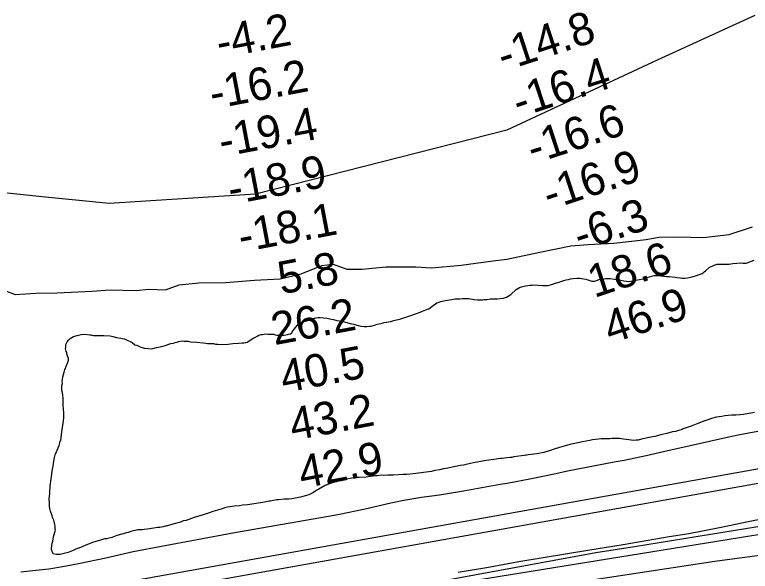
# Model space of a CAD drawing. Extents: x 3146026 to 3183936, y 897894 to 923344.
# Drawn here: x 3160766 to 3162279, y 910893 to 912037 of the extents above; entities that cross this region are included whole.
import ezdxf

# ---------------------------------------------------------------- set-up
doc = ezdxf.new("R2010")
doc.units = 0
for name, color, linetype in [('V-LEVE-TOET', 7, 'Continuous'), ('V-RIVR-EDGE', 7, 'Continuous'), ('V-RIVR-RANG', 7, 'Continuous'), ('V-ROAD-CNTR', 7, 'Continuous'), ('V-SITE-VEGE', 7, 'Continuous'), ('V-SURV-LINE', 7, 'Continuous'), ('V-TOPO-BNDY', 7, 'Continuous'), ('V-TOPO-SHOR', 7, 'Continuous')]:
    doc.layers.add(name, color=color, linetype=linetype)

msp = doc.modelspace()

# ---------------------------------------------------------------- linework, layer by layer
at = {"layer": 'V-LEVE-TOET'}
for points in [[(3162313.2, 911183.9), (3162257.1, 911173.5), (3162240.8, 911170.2), (3162109.2, 911140.5), (3162064.7, 911129.9), (3162019.8, 911120.8), (3161999.2, 911117.2), (3161902.9, 911098.3), (3161879, 911093.4), (3161829.2, 911082.6), (3161779, 911073.4), (3161764.6, 911071), (3161689.1, 911057.2), (3161639.6, 911049), (3161602.9, 911044.4), (3161566.5, 911038.3), (3161539.7, 911032.7), (3161487.2, 911020.2), (3161434.4, 911009.3), (3161423.5, 911007.3), (3161301.1, 910986.1), (3161215, 910971.3), (3161068.4, 910944), (3161010.1, 910933.1), (3160953.9, 910919.6), (3160901, 910908.5), (3160868.7, 910902.5), (3160836.2, 910897.5), (3160803.6, 910893.6), (3160779, 910891.2)], [(3162298.7, 910999.1), (3162277.9, 910995.3), (3162215.3, 910981.9), (3162152.3, 910970.1), (3162112.2, 910963.4), (3162017.4, 910946.9), (3161949.2, 910935.9), (3161802.9, 910912.3), (3161740.6, 910900.4), (3161678, 910890.1)]]:
    msp.add_lwpolyline(points, dxfattribs=at)
at = {"layer": 'V-RIVR-EDGE'}
msp.add_lwpolyline([(3160745.7, 911470), (3160767.1, 911462), (3160809.6, 911464.3), (3160853.6, 911465.4), (3160924.6, 911468.4), (3160962.3, 911471.5), (3161016.2, 911469.8), (3161041.6, 911472.5), (3161076.1, 911471.2), (3161104.7, 911481.8), (3161144.7, 911485.7), (3161200.3, 911486.3), (3161259.4, 911491.4), (3161312.1, 911494), (3161355.4, 911504.2), (3161397.8, 911521.6), (3161421.3, 911524.3), (3161449.4, 911513.9), (3161480.7, 911513.8), (3161529.5, 911518.8), (3161591.4, 911518.3), (3161623.5, 911516.6), (3161684.6, 911522), (3161744.5, 911530.2), (3161778.2, 911534.1), (3161846.1, 911548.6), (3161910, 911561.5), (3161945.3, 911564.2), (3161998.4, 911567.3), (3162064.7, 911574.6), (3162090.8, 911579.3), (3162130.5, 911580.4), (3162182.5, 911578.7), (3162235.2, 911584.9), (3162283.2, 911600.7)], dxfattribs=at)
at = {"layer": 'V-ROAD-CNTR'}
msp.add_lwpolyline([(3162638.2, 911023.4), (3161582.1, 910852.6), (3160471.1, 910632.1), (3159717.3, 910482.4)], dxfattribs=at)
at = {"layer": 'V-SITE-VEGE'}
for points in [[(3161758.3, 911453), (3161771.3, 911454.3), (3161777.6, 911456.5), (3161780.9, 911458.1), (3161786.4, 911462), (3161797.6, 911472.1), (3161804.3, 911476.3), (3161808.1, 911477.6), (3161816.5, 911479.7), (3161826.5, 911481.1), (3161829.5, 911481.1), (3161833.7, 911481.9), (3161851.3, 911480.4), (3161859.3, 911480), (3161862.6, 911480.4), (3161868.1, 911481.7), (3161874.3, 911483.4), (3161880.6, 911485.6), (3161884, 911486.4), (3161891.5, 911489), (3161895.3, 911490.7), (3161900.3, 911492), (3161904.9, 911492.8), (3161909.5, 911494.1), (3161914.1, 911494.6), (3161922.1, 911495), (3161927.6, 911495), (3161940.6, 911493), (3161952.8, 911488.9), (3161955.7, 911488.9), (3161959.1, 911489.4), (3161962.4, 911490.2), (3161967.9, 911492.3), (3161978.3, 911494.1), (3161981.7, 911494.9), (3161984.6, 911494.9), (3161988, 911494.5), (3161990.9, 911494.6), (3161999.7, 911493.4), (3162004.4, 911492.5), (3162006.5, 911492.6), (3162012.8, 911491.3), (3162018.6, 911489.7), (3162024.5, 911488.9), (3162029.1, 911488.5), (3162043.8, 911491.1), (3162051.3, 911492.8), (3162058.5, 911494.1), (3162062.2, 911495), (3162071.5, 911497.9), (3162081.1, 911500.5), (3162089.5, 911501), (3162106.7, 911499), (3162112.6, 911498.6), (3162124.3, 911497.4), (3162127.7, 911496.6), (3162135.7, 911495.8), (3162138.2, 911495.4), (3162144.5, 911495.4), (3162149.9, 911495.9), (3162159.6, 911498), (3162165.9, 911500.2), (3162174.2, 911502.7), (3162179.7, 911504.8), (3162182.2, 911506.5), (3162183.8, 911508.2), (3162186.8, 911510.3), (3162194.3, 911517.1), (3162204.8, 911522.2), (3162211, 911523.9), (3162226.1, 911524.4), (3162232.4, 911524), (3162234.9, 911524), (3162242.9, 911525.8), (3162259.7, 911526.7), (3162264.3, 911526.3), (3162270.2, 911526.3), (3162272.7, 911526.8), (3162286.9, 911532.3)], [(3161114.7, 911365.9), (3161122.7, 911365.5), (3161127.7, 911364.7), (3161140.8, 911364), (3161153.8, 911362.3), (3161159.2, 911362), (3161163, 911361.1), (3161168, 911361.2), (3161175.2, 911360.8), (3161179.4, 911360), (3161184, 911359.6), (3161194.1, 911359.2), (3161205, 911359.7), (3161215, 911361), (3161227.2, 911361.5), (3161233.9, 911362.4), (3161237.3, 911362.4), (3161240.2, 911363.2), (3161242.3, 911363.3), (3161244.4, 911364.1), (3161257.8, 911372.6), (3161259.9, 911373.4), (3161264.9, 911376), (3161268.2, 911378.1), (3161273.2, 911379.8), (3161275.8, 911379.8), (3161282.9, 911380.7), (3161286.7, 911380.3), (3161295.1, 911380.3), (3161299.3, 911379.9), (3161302.2, 911379.1), (3161305.6, 911377.9), (3161311.9, 911377.9), (3161320.7, 911378), (3161327, 911379.3), (3161329, 911380.1), (3161333.2, 911381), (3161336.2, 911383.1), (3161337, 911385.2), (3161339.1, 911387.7), (3161347, 911398.2), (3161351.2, 911402.5), (3161358.3, 911406.3), (3161361.6, 911406.3), (3161369.2, 911408), (3161372.9, 911409.3), (3161378.4, 911411.4), (3161385.5, 911413.6), (3161390.5, 911414.4), (3161394.7, 911414.5), (3161408.2, 911412.9), (3161417.8, 911411.2), (3161421.6, 911410.4), (3161428.8, 911408.4), (3161434.2, 911407.5), (3161438.8, 911406.7), (3161441.8, 911406.3), (3161446.8, 911404.7), (3161459, 911401.4), (3161463.6, 911400.6), (3161469.5, 911398.5), (3161472.9, 911398.1), (3161477.9, 911396.5), (3161485, 911395.7), (3161490.5, 911395.7), (3161496.8, 911396.6), (3161499.3, 911397), (3161508.1, 911399.6), (3161511.9, 911400.8), (3161515.6, 911401.7), (3161521.9, 911402.6), (3161526.1, 911403.9), (3161539.5, 911406.5), (3161546.2, 911408.2), (3161560.1, 911412), (3161574.7, 911416.7), (3161596.5, 911424.4), (3161604.9, 911427.8), (3161608.2, 911428.7), (3161611.6, 911429.9), (3161615.3, 911431.6), (3161617.8, 911432.1), (3161623.7, 911437.1), (3161634.6, 911444.3), (3161637.1, 911445.2), (3161642.5, 911447.7), (3161651.7, 911449.5), (3161665.2, 911451.2), (3161672.3, 911452.5), (3161676.5, 911453), (3161681.9, 911453), (3161687.4, 911453.4), (3161700, 911453.5), (3161710.9, 911451.5), (3161717.6, 911450.7), (3161728.9, 911450.7), (3161731.9, 911451.6), (3161736.9, 911451.6), (3161744.4, 911452.5), (3161754.5, 911453), (3161758.3, 911453)], [(3160846.7, 910966.7), (3160849.6, 910975.1), (3160850, 910977.2), (3160849.6, 910979.3), (3160849.6, 910983.5), (3160848.7, 910989.3), (3160847.4, 910995.2), (3160846.6, 910998.1), (3160844, 911003.6), (3160843.2, 911006.9), (3160839.8, 911016.5), (3160838.5, 911021.6), (3160837.6, 911026.6), (3160837.6, 911033.7), (3160837.1, 911041.3), (3160838.3, 911053), (3160838.3, 911055.1), (3160839, 911067.7), (3160841.1, 911082.8), (3160844.3, 911102.6), (3160845.5, 911108.9), (3160845.9, 911114.8), (3160847.9, 911126.9), (3160849.2, 911132), (3160857.9, 911151.7), (3160859.9, 911159.3), (3160860.8, 911163.1), (3160862.4, 911173.2), (3160864, 911184.9), (3160864.4, 911188.7), (3160866, 911197.1), (3160866.4, 911202.6), (3160867.2, 911208.4), (3160867.2, 911215.6), (3160866.7, 911229), (3160866.2, 911231.5), (3160865.8, 911236.1), (3160865.8, 911244.5), (3160865.7, 911248.7), (3160865.3, 911254.2), (3160864.4, 911260), (3160863.5, 911264.2), (3160863.5, 911268.8), (3160863.1, 911270.9), (3160863.5, 911273.9), (3160864.3, 911278.9), (3160863.9, 911282.7), (3160864.7, 911286.9), (3160865.5, 911292.8), (3160867.9, 911302.4), (3160869.6, 911307.5), (3160870.4, 911309.6), (3160871.7, 911312.1), (3160872.5, 911315.5), (3160874.6, 911320.9), (3160877, 911326.8), (3160876.6, 911330.2), (3160875.7, 911333.5), (3160873.6, 911339.8), (3160873.2, 911342.7), (3160872.3, 911344.8), (3160871, 911350.3), (3160871.4, 911353.2), (3160871.4, 911357.8), (3160872.2, 911360.4), (3160874.3, 911364.6), (3160876.8, 911367.9), (3160878.5, 911369.2), (3160880.6, 911371.3), (3160887.3, 911375.1), (3160894.4, 911377.3), (3160902.8, 911379.4), (3160910.7, 911379.9), (3160920.8, 911378.7), (3160922.9, 911378.7), (3160925, 911377.9), (3160928, 911377.5), (3160949.3, 911377.6), (3160962.4, 911376.8), (3160968.2, 911375.2), (3160975.4, 911373.5), (3160984.6, 911371.9), (3160991.3, 911370.3), (3161004, 911364.9), (3161007.7, 911362.8), (3161013.6, 911358.6), (3161017.4, 911357.4), (3161025.4, 911353.7), (3161033, 911351.2), (3161047.7, 911350), (3161050.6, 911350.9), (3161057.7, 911352.6), (3161069.1, 911354.7), (3161073.7, 911356), (3161087.5, 911360.7), (3161092.9, 911361.6), (3161096.3, 911362.9), (3161100.5, 911364.1), (3161103.4, 911365.4), (3161110.9, 911366.3), (3161114.7, 911365.9)], [(3162287.4, 911218.9), (3162265.2, 911215), (3162257.7, 911214.1), (3162249.3, 911214), (3162240.5, 911213.6), (3162226.6, 911212.2), (3162220.3, 911210.9), (3162209.4, 911209.6), (3162199.4, 911206.6), (3162189.7, 911203.2), (3162185.1, 911201.9), (3162171.3, 911196.8), (3162157.1, 911190.9), (3162140.8, 911185.8), (3162138.7, 911184.5), (3162136.6, 911183.6), (3162131.1, 911181.9), (3162124.8, 911180.2), (3162119, 911179.3), (3162107.2, 911176.3), (3162101.4, 911174.6), (3162095.1, 911173.3), (3162082.9, 911169.9), (3162071.2, 911167.7), (3162055.3, 911164.3), (3162048.6, 911162.6), (3162044.4, 911162.6), (3162038.5, 911161.7), (3162028.9, 911163.3), (3162017.9, 911164.5), (3162010, 911165.7), (3161994.9, 911165.6), (3161989.8, 911165.2), (3161972.2, 911165.1), (3161966.7, 911164.2), (3161960.9, 911163.8), (3161954.2, 911162.9), (3161948.7, 911161.6), (3161933.6, 911159), (3161914.8, 911154.7), (3161908.1, 911153.4), (3161900.9, 911151.7), (3161895.9, 911150), (3161886.3, 911147.4), (3161875.8, 911143.6), (3161867.4, 911141), (3161865.3, 911140.6), (3161854.5, 911137.2), (3161839.8, 911134.1), (3161822.2, 911131.9), (3161819.7, 911131.5), (3161817.6, 911131.5), (3161814.2, 911131.1), (3161792.8, 911128), (3161788.2, 911126.7), (3161784.4, 911126.7), (3161768.1, 911124.9), (3161765.2, 911124.9), (3161751.3, 911122.7), (3161735.8, 911120.6), (3161709.4, 911115.8), (3161697.2, 911112.8), (3161689.3, 911111.1), (3161683, 911110.2), (3161669.2, 911107.6), (3161653.7, 911104.2), (3161647, 911103.3), (3161640.2, 911101.6), (3161630.2, 911099.8)], [(3161630.2, 911099.8), (3161623.5, 911098.1), (3161585.8, 911092.9), (3161572.8, 911092), (3161564.8, 911091.9), (3161545.5, 911090.5), (3161538.4, 911090.5), (3161533.7, 911090.1), (3161525.3, 911090), (3161520.3, 911090.4), (3161511.9, 911089.1), (3161508.2, 911089.1), (3161503.5, 911088.2), (3161498.1, 911087.8), (3161488.9, 911086.5), (3161474.6, 911085.5), (3161468.7, 911085.5), (3161455.7, 911083.3), (3161449.4, 911082.5), (3161443.2, 911081.2), (3161430.2, 911078.2), (3161427.7, 911076.9), (3161424.7, 911076), (3161419.3, 911074.7), (3161404.6, 911069.2), (3161391.7, 911061.6), (3161387.5, 911059.5), (3161383.3, 911056.9), (3161380.4, 911054.8), (3161371.2, 911050.1), (3161359, 911046.3), (3161354, 911045.4), (3161336.4, 911041.6), (3161330.1, 911041.1), (3161320.4, 911041), (3161308.7, 911039.7), (3161304.9, 911039.7), (3161292.4, 911037.1), (3161289.4, 911037.1), (3161280.2, 911034.9), (3161258.8, 911031.5), (3161245, 911029.7), (3161234.5, 911028.8), (3161228.2, 911027.5), (3161218.2, 911026.6), (3161203.9, 911024.5), (3161197.6, 911023.2), (3161192.6, 911021.5), (3161173.7, 911015.9), (3161162.4, 911011.6), (3161159.9, 911011.2), (3161153.6, 911009.1), (3161135.6, 911003.5), (3161124.3, 910999.2), (3161118.9, 910997.5), (3161113, 910996.3), (3161107.1, 910994.1), (3161091.2, 910989.4), (3161080.3, 910986), (3161078.2, 910986), (3161071.5, 910984.3), (3161064.4, 910983), (3161060.2, 910982.5), (3161052.7, 910981.2), (3161038.4, 910979.5), (3161032.5, 910979), (3161028.4, 910978.2), (3161024.6, 910978.1), (3161019.5, 910977.7), (3161005.3, 910974.3), (3160999.4, 910972.5), (3160995.2, 910972.1), (3160989, 910970), (3160976, 910966.1), (3160973, 910964.8), (3160965.9, 910962.3), (3160959.6, 910961), (3160955, 910959.7), (3160950.8, 910959.3), (3160945, 910957.6), (3160935.8, 910954.6), (3160928.6, 910952.4), (3160919.4, 910949), (3160911.5, 910945.6), (3160907.7, 910944.3), (3160905.2, 910943.1), (3160892.2, 910938), (3160886.8, 910935.4), (3160876.3, 910931.2), (3160860, 910927.3), (3160851.6, 910927.2), (3160845.7, 910928.5), (3160844.4, 910930.1), (3160842.3, 910935.6), (3160841.9, 910937.7), (3160841.9, 910940.2), (3160843.5, 910950.7), (3160844.7, 910954.9), (3160845.5, 910958.7), (3160845.9, 910962.9), (3160846.7, 910966.7)]]:
    msp.add_lwpolyline(points, dxfattribs=at)
at = {"layer": 'V-SURV-LINE'}
for points in [[(3160812, 910838.1), (3162611, 911160.1)], [(3162616.3, 911130.6), (3160817.3, 910808.6)]]:
    msp.add_lwpolyline(points, dxfattribs=at)
at = {"layer": 'V-TOPO-BNDY'}
msp.add_lwpolyline([(3162288, 912035.1), (3162225.5, 912006.3), (3162087.3, 911943.2), (3161778.1, 911799.8), (3161261.5, 911668.3), (3160960.6, 911648.5), (3160815.9, 911663.3), (3160685.6, 911676.6), (3160605.9, 911700), (3160140.6, 911840.9), (3159445.2, 912129.3), (3158861.9, 912432.7), (3158245.4, 912823.6), (3157767.9, 913092.7), (3157135.3, 913454.6), (3156545.8, 913785.7)], dxfattribs=at)
at = {"layer": 'V-TOPO-SHOR'}
for points in [[(3161817.9, 910855), (3162205.8, 910913.4), (3162468, 910948.7), (3162571.9, 910962.8), (3162674.7, 910982.9), (3162741.4, 911001.6), (3162791.3, 911020.8), (3162871.8, 911062), (3162922, 911093.2), (3162967.5, 911131.7), (3163020.4, 911174.9)], [(3161010.6, 910750.8), (3161223.2, 910794.6), (3161435.7, 910835.1), (3161600.2, 910864.9), (3161961, 910931.3), (3162040.6, 910943.7), (3162294.1, 910984.7)]]:
    msp.add_lwpolyline(points, dxfattribs=at)

# ---------------------------------------------------------------- texts
at = {"layer": 'V-RIVR-RANG'}
for s, rotation, p in [('-4.2', 10.7483, (3161187.1, 911946.6)), ('-14.8', 18.1483, (3161771.2, 911919.5)), ('-16.2', 10.7483, (3161173.3, 911842.2)), ('-16.4', 18.1483, (3161802.6, 911824.5)), ('-16.6', 18.1483, (3161832.2, 911729)), ('-19.4', 10.7483, (3161192.2, 911744)), ('-18.9', 10.7483, (3161210.8, 911645.8)), ('-16.9', 18.1483, (3161865.1, 911634.5)), ('-6.3', 18.1483, (3161928.3, 911550)), ('-18.1', 10.7483, (3161232.3, 911548)), ('18.6', 18.1483, (3161958, 911454.5)), ('5.8', 10.7483, (3161314.2, 911461.8)), ('46.9', 18.1483, (3161990.9, 911360.1)), ('26.2', 10.7483, (3161300.4, 911357.4)), ('40.5', 10.7483, (3161319.3, 911259.2)), ('43.2', 10.7483, (3161338.2, 911161)), ('42.9', 10.7483, (3161356.8, 911062.7))]:
    msp.add_text(s, height=67, rotation=rotation, dxfattribs=at).set_placement(p)

doc.saveas('drawing.dxf')
